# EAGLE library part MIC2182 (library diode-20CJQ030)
MICREL's MIC2182
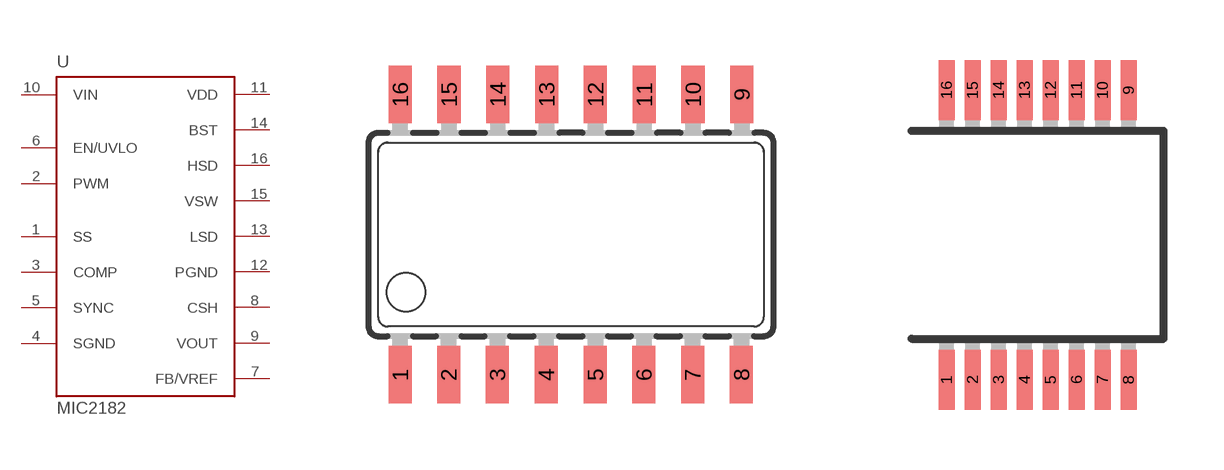
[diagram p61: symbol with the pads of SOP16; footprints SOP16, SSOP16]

Designator prefix U

## MIC2182SOP16  [SOP16]
1  SS  in
2  PWM  in
3  COMP  out
4  SGND  pwr
5  SYNC  in
6  EN/UVLO  in
7  FB/VREF
8  CSH  in
9  VOUT  in
10  VIN  pwr
11  VDD  out
12  PGND  pwr
13  LSD  out
14  BST  in
15  VSW  out
16  HSD  out

## MIC2182SSOP16  [SSOP16]
Pads as for SOP16

## Footprint SOP16 (pad centres in mm)
Small Outline Package
smd 0.6 x 1.5: 1 -4.445,-3.65; 2 -3.185,-3.65; 3 -1.915,-3.65; 4 -0.645,-3.65; 5 0.635,-3.65; 6 1.895,-3.65; 7 3.165,-3.65; 8 4.435,-3.65; 9 4.445,3.65; 10 3.175,3.65; 11 1.905,3.65; 12 0.635,3.65; 13 -0.635,3.65; 14 -1.905,3.65; 15 -3.175,3.65; 16 -4.445,3.65

## Footprint SSOP16 (pad centres in mm)
Shrink Small Outline Package package type SS
smd 0.4 x 1.5: 1 -2.275,-3.625; 2 -1.625,-3.625; 3 -0.975,-3.625; 4 -0.325,-3.625; 5 0.325,-3.625; 6 0.975,-3.625; 7 1.625,-3.625; 8 2.275,-3.625; 9 2.275,3.625; 10 1.625,3.625; 11 0.975,3.625; 12 0.325,3.625; 13 -0.325,3.625; 14 -0.975,3.625; 15 -1.625,3.625; 16 -2.275,3.625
